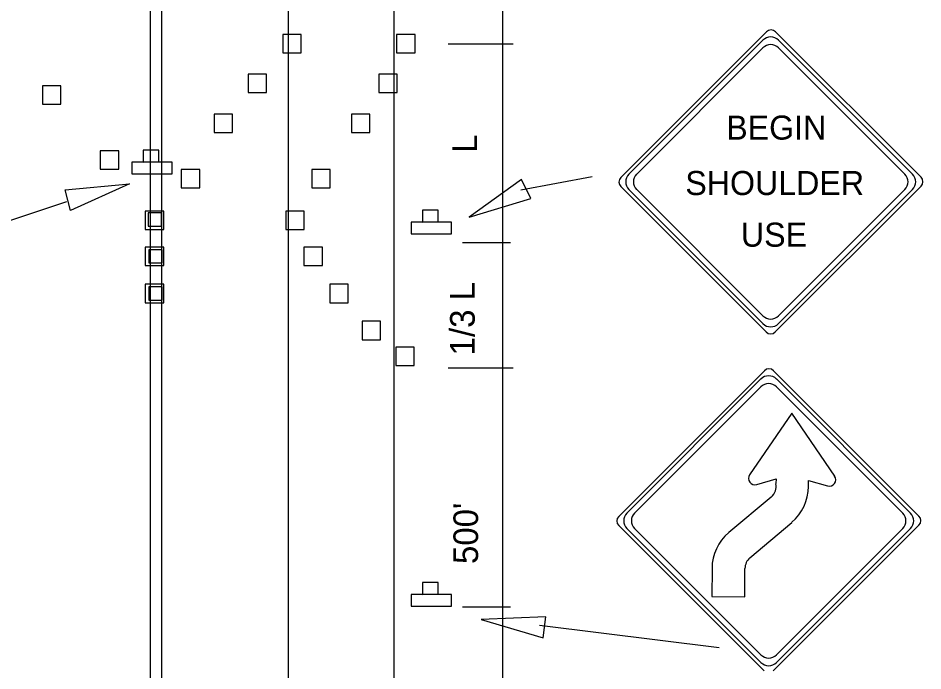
# Model space of a CAD drawing. Extents: x 1531.38 to 1538.58, y 1529.59 to 1539.28.
# Drawn here: x 1535.582 to 1537.784, y 1533.489 to 1535.077 of the extents above; entities that cross this region are included whole.
import ezdxf

# ---------------------------------------------------------------- set-up
doc = ezdxf.new("R2010")
doc.units = 0
for name, color, linetype in [('DETL-DIMS', 7, 'Continuous'), ('DETL-LINE', 7, 'Continuous'), ('DETL-NOTE', 7, 'Continuous'), ('USER-BORD', 7, 'Continuous')]:
    doc.layers.add(name, color=color, linetype=linetype)

# ---------------------------------------------------------------- blocks, each defined once
blk = doc.blocks.new('CD20')
at = {"layer": 'USER-BORD'}
blk.add_lwpolyline([(-0.0625, -0.0625), (0, -0.0625), (0, 0), (-0.0625, 0)], close=True, dxfattribs=at)
blk = doc.blocks.new('SIGN13')
at = {"layer": 'USER-BORD'}
for points in [[(-0.0134, 0.0182), (0.011, 0.0189), (0.011, 0.0371), (-0.0134, 0.0371)], [(-0.0314, 0.0182), (-0.0314, 0), (0.032, 0), (0.032, 0.0182)]]:
    blk.add_lwpolyline(points, close=True, dxfattribs=at)

msp = doc.modelspace()

# ---------------------------------------------------------------- linework, layer by layer
at = {"layer": 'DETL-DIMS'}
for p, q in [((1536.7613, 1535.4484), (1536.7613, 1533.1366)), ((1536.6291, 1535.0143), (1536.7871, 1535.0143)), ((1536.8054, 1534.659), (1536.9792, 1534.6922)), ((1535.6998, 1534.63), (1535.0012, 1534.3974)), ((1536.6639, 1534.5316), (1536.7804, 1534.5316)), ((1536.7613, 1534.4003), (1536.7613, 1532.2659)), ((1536.6291, 1534.2265), (1536.7871, 1534.2265)), ((1536.6639, 1533.6446), (1536.7804, 1533.6446)), ((1536.8507, 1533.6001), (1537.2877, 1533.5459))]:
    msp.add_line(p, q, dxfattribs=at)
for points in [[(1536.8302, 1534.6385), (1536.8072, 1534.6848), (1536.6798, 1534.5927)], [(1535.7098, 1534.6093), (1535.6966, 1534.6593), (1535.8531, 1534.6739)], [(1536.8601, 1533.5693), (1536.8665, 1533.6206), (1536.7094, 1533.614)]]:
    msp.add_lwpolyline(points, close=True, dxfattribs=at)
at = {"layer": 'DETL-LINE'}
for p, q in [((1535.9039, 1538.9346), (1535.9039, 1531.7918)), ((1535.9309, 1538.9346), (1535.9309, 1531.7918)), ((1536.4962, 1538.9346), (1536.4962, 1531.7918)), ((1536.2393, 1535.6775), (1536.2393, 1531.8053)), ((1537.4033, 1535.0441), (1537.0486, 1534.6894)), ((1537.7792, 1534.6901), (1537.4253, 1535.0441)), ((1537.0685, 1534.6977), (1537.3947, 1535.0239)), ((1537.4324, 1535.0239), (1537.7585, 1534.6977)), ((1537.3947, 1535.0051), (1537.0874, 1534.6977)), ((1537.7397, 1534.6977), (1537.4323, 1535.0051)), ((1537.7397, 1534.6977), (1537.7397, 1534.6977)), ((1537.0486, 1534.6674), (1537.4025, 1534.3135)), ((1537.3947, 1534.3339), (1537.0685, 1534.66)), ((1537.0874, 1534.6601), (1537.3947, 1534.3527)), ((1537.4245, 1534.3135), (1537.7792, 1534.6682)), ((1537.7585, 1534.66), (1537.4324, 1534.3339)), ((1537.4324, 1534.3527), (1537.7397, 1534.66)), ((1537.3983, 1534.2193), (1537.0436, 1533.8646)), ((1537.7742, 1533.8653), (1537.4203, 1534.2193)), ((1537.0636, 1533.8729), (1537.3897, 1534.1991)), ((1537.4274, 1534.1991), (1537.7535, 1533.8729)), ((1537.3897, 1534.1803), (1537.0824, 1533.8729)), ((1537.7347, 1533.8729), (1537.4274, 1534.1803)), ((1537.4649, 1534.1163), (1537.3622, 1533.9661)), ((1537.5691, 1533.9629), (1537.4649, 1534.1163)), ((1537.3798, 1533.9421), (1537.4267, 1533.9563)), ((1537.4267, 1533.9563), (1537.4262, 1533.9444)), ((1537.5053, 1533.9375), (1537.5053, 1533.9519)), ((1537.5053, 1533.9519), (1537.5517, 1533.9388)), ((1537.4147, 1533.9119), (1537.3112, 1533.8252)), ((1537.7347, 1533.8729), (1537.7347, 1533.8729)), ((1537.0436, 1533.8426), (1537.3976, 1533.4887)), ((1537.3628, 1533.764), (1537.4647, 1533.8502)), ((1537.4195, 1533.4887), (1537.7742, 1533.8434)), ((1537.3897, 1533.5091), (1537.0636, 1533.8352)), ((1537.0824, 1533.8353), (1537.3897, 1533.5279)), ((1537.7535, 1533.8352), (1537.4274, 1533.5091)), ((1537.4274, 1533.5279), (1537.7347, 1533.8352)), ((1537.2707, 1533.738), (1537.2706, 1533.6695)), ((1537.3507, 1533.6693), (1537.3507, 1533.7379)), ((1537.2706, 1533.6695), (1537.3507, 1533.6693))]:
    msp.add_line(p, q, dxfattribs=at)
for points in [[(1536.2262, 1534.9929), (1536.271, 1534.9929), (1536.271, 1535.0377), (1536.2262, 1535.0377)], [(1536.5033, 1534.9929), (1536.5481, 1534.9929), (1536.5481, 1535.0377), (1536.5033, 1535.0377)], [(1536.1421, 1534.8959), (1536.1869, 1534.8959), (1536.1869, 1534.9407), (1536.1421, 1534.9407)], [(1536.4597, 1534.8959), (1536.5045, 1534.8959), (1536.5045, 1534.9407), (1536.4597, 1534.9407)], [(1535.6416, 1534.8678), (1535.6864, 1534.8678), (1535.6864, 1534.9126), (1535.6416, 1534.9126)], [(1536.0592, 1534.7989), (1536.104, 1534.7989), (1536.104, 1534.8437), (1536.0592, 1534.8437)], [(1536.3932, 1534.7989), (1536.438, 1534.7989), (1536.438, 1534.8437), (1536.3932, 1534.8437)], [(1535.7824, 1534.7097), (1535.8272, 1534.7097), (1535.8272, 1534.7545), (1535.7824, 1534.7545)], [(1535.9795, 1534.6644), (1536.0243, 1534.6644), (1536.0243, 1534.7092), (1535.9795, 1534.7092)], [(1536.297, 1534.6644), (1536.3418, 1534.6644), (1536.3418, 1534.7092), (1536.297, 1534.7092)], [(1535.8919, 1534.5627), (1535.9367, 1534.5627), (1535.9367, 1534.6075), (1535.8919, 1534.6075)], [(1536.234, 1534.5627), (1536.2788, 1534.5627), (1536.2788, 1534.6075), (1536.234, 1534.6075)], [(1535.8919, 1534.4751), (1535.9367, 1534.4751), (1535.9367, 1534.5199), (1535.8919, 1534.5199)], [(1536.2778, 1534.4751), (1536.3226, 1534.4751), (1536.3226, 1534.5199), (1536.2778, 1534.5199)], [(1535.8919, 1534.3847), (1535.9367, 1534.3847), (1535.9367, 1534.4295), (1535.8919, 1534.4295)], [(1536.3407, 1534.3847), (1536.3855, 1534.3847), (1536.3855, 1534.4295), (1536.3407, 1534.4295)], [(1536.4194, 1534.2946), (1536.4642, 1534.2946), (1536.4642, 1534.3394), (1536.4194, 1534.3394)], [(1536.5014, 1534.232), (1536.5462, 1534.232), (1536.5462, 1534.2768), (1536.5014, 1534.2768)]]:
    msp.add_lwpolyline(points, close=True, dxfattribs=at)
for centre, radius, start, end in [((1537.4135, 1535.005), 0.0266, 45, 135), ((1537.4143, 1535.0331), 0.0155, 45, 135), ((1537.4135, 1534.9862), 0.0266, 45, 135), ((1537.0596, 1534.6784), 0.0155, 135, 225), ((1537.0873, 1534.6788), 0.0266, 135, 225), ((1537.1061, 1534.6789), 0.0266, 135, 225), ((1537.7209, 1534.6788), 0.0266, 315, 45), ((1537.7397, 1534.6788), 0.0266, 315, 45), ((1537.7682, 1534.6792), 0.0155, 315, 45), ((1537.4135, 1534.3715), 0.0266, 225, 315), ((1537.4135, 1534.3526), 0.0266, 225, 315), ((1537.4135, 1534.3244), 0.0155, 225, 315), ((1537.4093, 1534.2083), 0.0155, 45, 135), ((1537.4086, 1534.1802), 0.0266, 45, 135), ((1537.4085, 1534.1614), 0.0266, 45, 135), ((1537.3752, 1533.9572), 0.0157, 145.6457, 286.8036), ((1537.556, 1533.954), 0.0157, 254.4164, 34.1664), ((1537.3925, 1533.938), 0.0343, 310.2409, 10.6511), ((1537.3908, 1533.9376), 0.1144, 310.2409, 359.906), ((1537.0546, 1533.8536), 0.0155, 135, 225), ((1537.0824, 1533.854), 0.0266, 135, 225), ((1537.1012, 1533.8541), 0.0266, 135, 225), ((1537.7159, 1533.854), 0.0266, 315, 45), ((1537.7348, 1533.854), 0.0266, 315, 45), ((1537.7633, 1533.8544), 0.0155, 315, 45), ((1537.3851, 1533.7378), 0.1144, 130.2409, 179.906), ((1537.3851, 1533.7378), 0.0343, 130.2409, 179.906), ((1537.4086, 1533.5467), 0.0266, 225, 315), ((1537.4086, 1533.5278), 0.0266, 225, 315)]:
    msp.add_arc(centre, radius, start, end, dxfattribs=at)

# ---------------------------------------------------------------- block references
for name, p, xscale, yscale in [('SIGN13', (1535.9074, 1534.6986), 1.550372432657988, 1.550372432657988), ('CD20', (1535.931, 1534.6035), 0.5153677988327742, 0.5153677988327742), ('SIGN13', (1536.5873, 1534.5526), 1.550372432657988, 1.550372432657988), ('CD20', (1535.9327, 1534.5136), 0.5153677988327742, 0.5153677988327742), ('CD20', (1535.9327, 1534.4232), 0.5153677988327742, 0.5153677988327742), ('SIGN13', (1536.5873, 1533.6465), 1.550372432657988, 1.550372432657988)]:
    msp.add_blockref(name, p, dxfattribs=dict(at, xscale=xscale, yscale=yscale))

# ---------------------------------------------------------------- texts
for s, p in [('BEGIN', (1537.3052, 1534.7816)), ('SHOULDER', (1537.2057, 1534.6467)), ('USE', (1537.341, 1534.521))]:
    msp.add_text(s, height=0.05854, dxfattribs=at).set_placement(p)
at = {"layer": 'DETL-NOTE'}
for s, p in [('L', (1536.6988, 1534.7496)), ('1/3 L', (1536.6934, 1534.2566)), ("500'", (1536.7015, 1533.7488))]:
    msp.add_text(s, height=0.06, rotation=90, dxfattribs=at).set_placement(p)

doc.saveas('drawing.dxf')
